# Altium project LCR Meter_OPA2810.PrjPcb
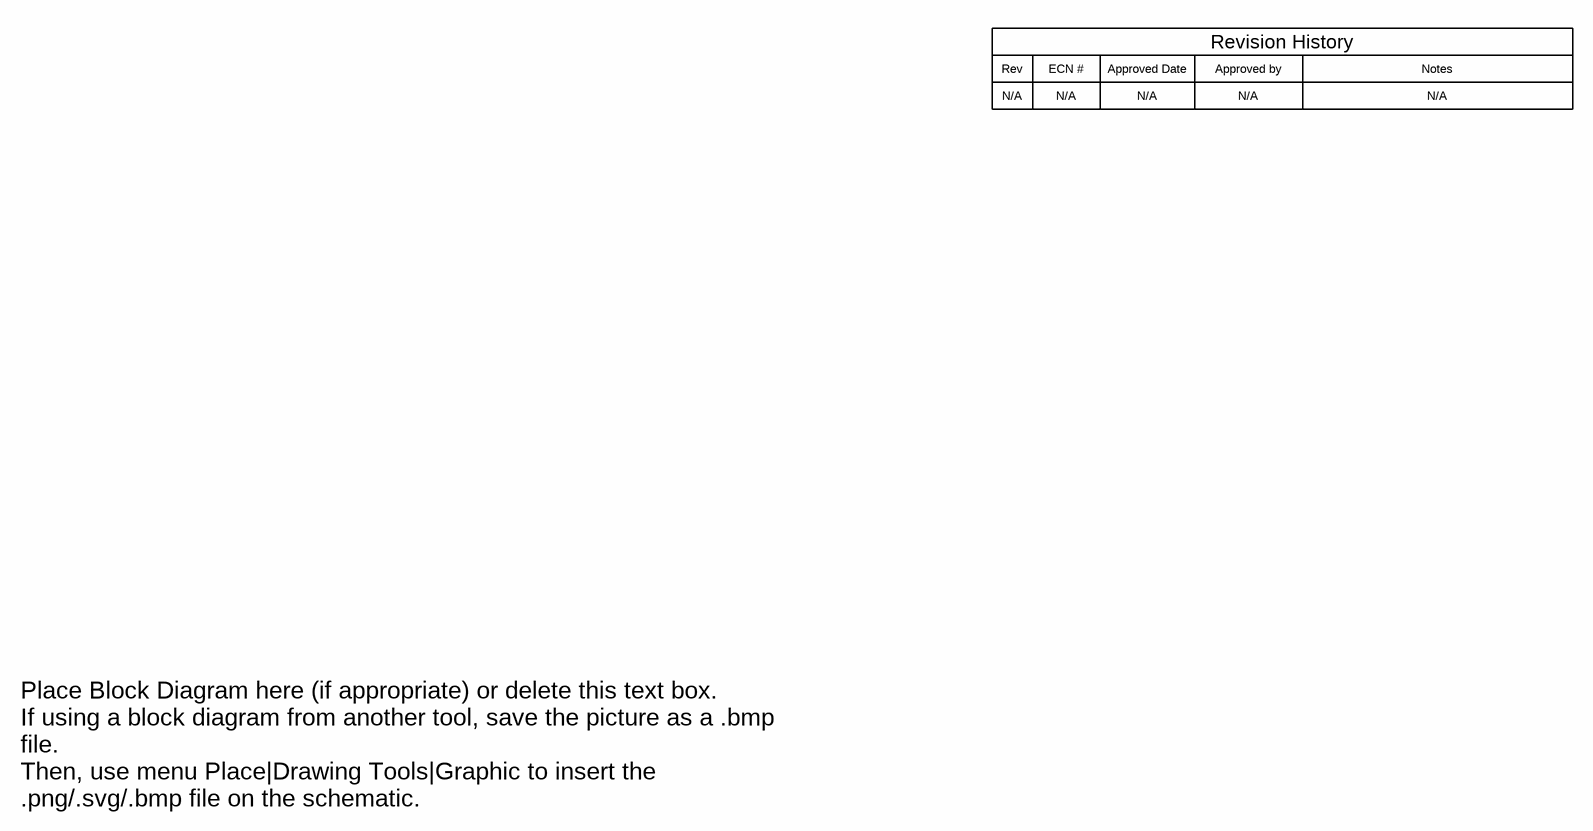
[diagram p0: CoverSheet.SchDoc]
CopyrightYear: 2018; PCB_Layout: Prasanth; PCB_Rev: _A; PRJ_Customer: Public Release; PRJ_Engineer: Adesh; PRJ_Number: LCR Meter_OPA2810; PRJ_Title: LCR Meter_OPA2810; SCH_Rev: _E1; TechSupport: http://www.ti.com/support; TID: N/A
5 sheets, 154 parts. Net scope: global (net labels, ports and power ports of the same name join across sheets).
Board file: LCR Meter_OPA2810_Rev_A.PcbDoc
Sheets:
  CoverSheet.SchDoc
  Power Supply.SchDoc
  BlankSheet.SchDoc
  EVM_Hardware.SchDoc
  VCA.SchDoc

## Sheet CoverSheet.SchDoc
size 431 x 279 mm; Date: Not shown in title block; ApprovedBy: Not shown in title block; CheckedBy: Not shown in title block; Author: Not shown in title block; CompanyName: Not shown in title block; Engineer: Not shown in title block; Organization: Not shown in title block; Address1: Not shown in title block; Address2: Not shown in title block; Address3: Not shown in title block; Address4: Not shown in title block; DocumentNumber: 1; Revision: Use project parameter SCH_Rev; SheetNumber: 1; SheetTotal: 3; PageSetup: Record=PageOptions¦CenterHorizontal=True¦CenterVertical=True¦PrintScale=1.00¦XCorrection=1.00¦YCorrection=1.00¦PrintKind=0¦BorderSize=5000000¦LeftOffset=0¦BottomOffset=0¦Orientation=2¦PaperLength=1000¦PaperWidth=1000¦Scale=100¦PaperSource=15¦PrintQuality=600¦MediaType=1¦DitherType=10¦PaperKind=Letter¦PrintScaleMode=1

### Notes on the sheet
- Rev
- N/A
- ECN #
- Approved Date
- Approved by
- Revision History
- Notes
- Place Block Diagram here (if appropriate) or delete this text box.
  If using a block diagram from another tool, save the picture as a .bmp file.
  Then, use menu Place|Drawing Tools|Graphic to insert the .png/.svg/.bmp file on the schematic.

## Sheet Power Supply.SchDoc
size 431 x 279 mm; Date: Not shown in title block; ApprovedBy: Not shown in title block; CheckedBy: Not shown in title block; Author: Not shown in title block; CompanyName: Not shown in title block; Engineer: Not shown in title block; Organization: Not shown in title block; Address1: Not shown in title block; Address2: Not shown in title block; Address3: Not shown in title block; Address4: Not shown in title block; DocumentNumber: 1; Revision: Use project parameter SCH_Rev; SheetNumber: 2; SheetTotal: 3; PageSetup: Record=PageOptions¦CenterHorizontal=True¦CenterVertical=True¦PrintScale=1.00¦XCorrection=1.00¦YCorrection=1.00¦PrintKind=0¦BorderSize=5000000¦LeftOffset=0¦BottomOffset=0¦Orientation=2¦PaperLength=1000¦PaperWidth=1000¦Scale=100¦PaperSource=15¦PrintQuality=600¦MediaType=1¦DitherType=10¦PaperKind=Letter¦PrintScaleMode=1

## Sheet BlankSheet.SchDoc
size 431 x 279 mm; Date: Not shown in title block; ApprovedBy: Not shown in title block; CheckedBy: Not shown in title block; Author: Not shown in title block; CompanyName: Not shown in title block; Engineer: Not shown in title block; Organization: Not shown in title block; Address1: Not shown in title block; Address2: Not shown in title block; Address3: Not shown in title block; Address4: Not shown in title block; DocumentNumber: 1; Revision: Use project parameter SCH_Rev; SheetNumber: 2; SheetTotal: 3; PageSetup: Record=PageOptions¦CenterHorizontal=True¦CenterVertical=True¦PrintScale=1.00¦XCorrection=1.00¦YCorrection=1.00¦PrintKind=0¦BorderSize=5000000¦LeftOffset=0¦BottomOffset=0¦Orientation=2¦PaperLength=1000¦PaperWidth=1000¦Scale=100¦PaperSource=15¦PrintQuality=600¦MediaType=1¦DitherType=10¦PaperKind=Letter¦PrintScaleMode=1
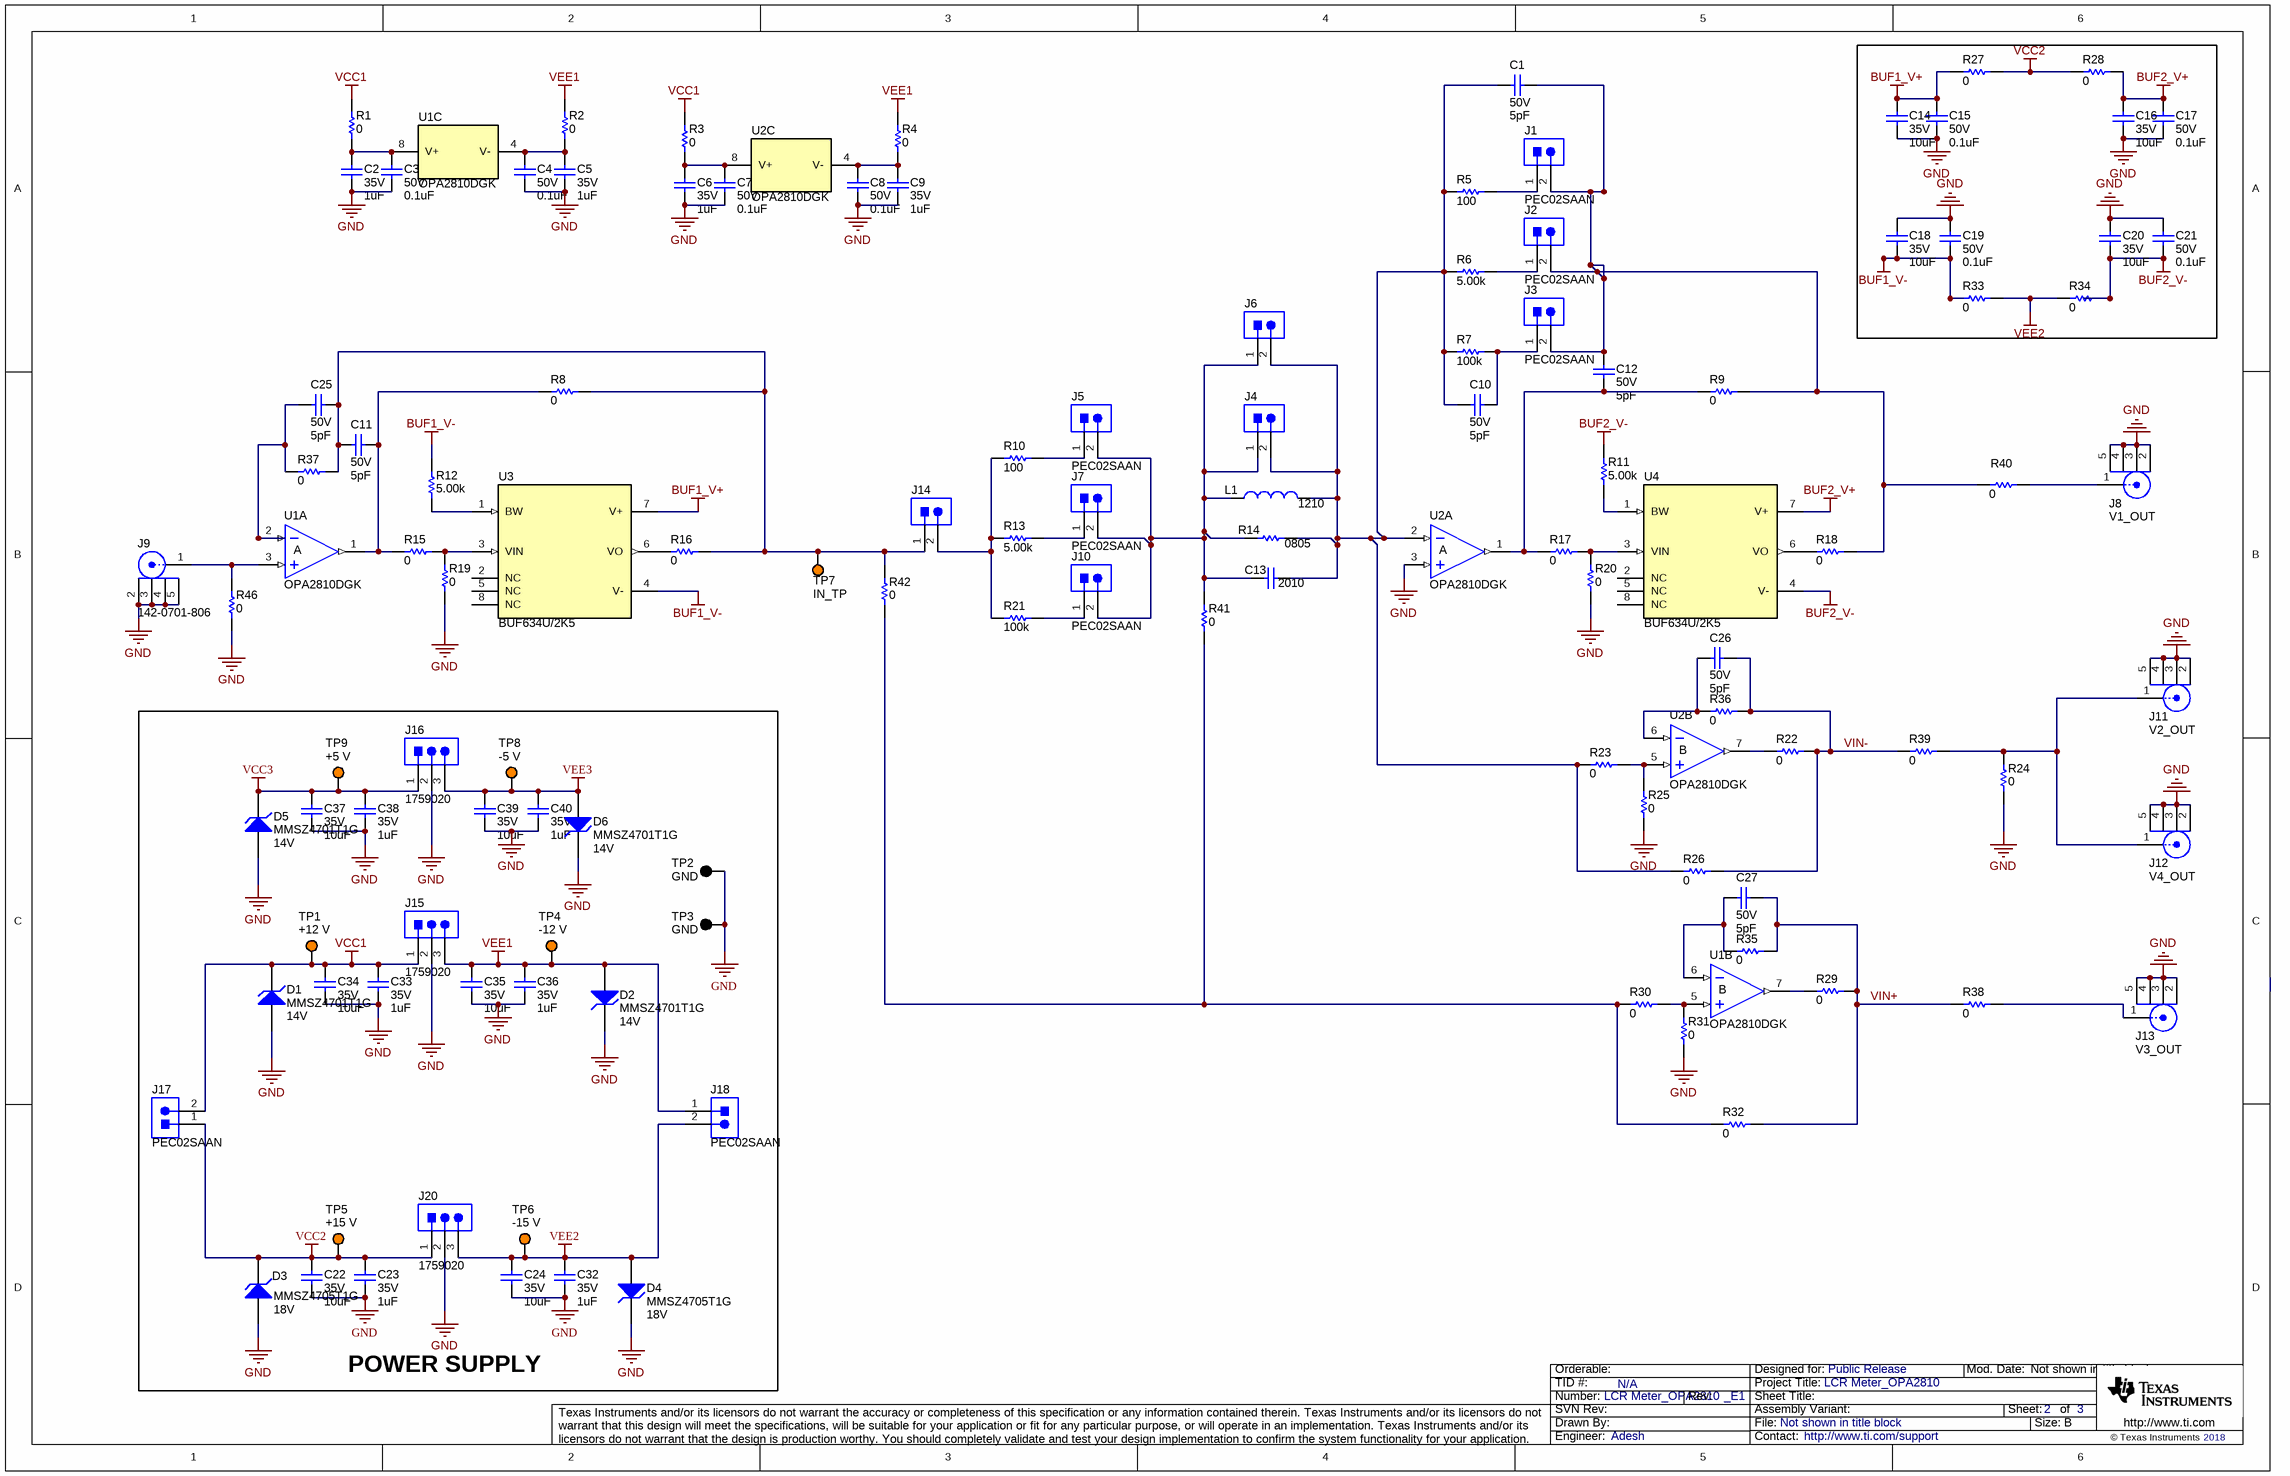
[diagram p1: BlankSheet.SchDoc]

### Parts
C1  VDC_V: 50V  ValueDisplayed: 5pF  [0402]  (hidden comment: GRM1555C1H5R0CA01D)
C2  VDC_V: 35V  ValueDisplayed: 1uF  [0603]  (hidden comment: C1608X7R1V105K080AC)
C3  VDC_V: 50V  ValueDisplayed: 0.1uF  [0603]  (hidden comment: GRM188R71H104KA93D)
C4  VDC_V: 50V  ValueDisplayed: 0.1uF  [0603]  (hidden comment: GRM188R71H104KA93D)
C5  VDC_V: 35V  ValueDisplayed: 1uF  [0603]  (hidden comment: C1608X7R1V105K080AC)
C6  VDC_V: 35V  ValueDisplayed: 1uF  [0603]  (hidden comment: C1608X7R1V105K080AC)
C7  VDC_V: 50V  ValueDisplayed: 0.1uF  [0603]  (hidden comment: GRM188R71H104KA93D)
C8  VDC_V: 50V  ValueDisplayed: 0.1uF  [0603]  (hidden comment: GRM188R71H104KA93D)
C9  VDC_V: 35V  ValueDisplayed: 1uF  [0603]  (hidden comment: C1608X7R1V105K080AC)
C10  VDC_V: 50V  ValueDisplayed: 5pF  [0402]  (hidden comment: GRM1555C1H5R0CA01D)
C11  VDC_V: 50V  ValueDisplayed: 5pF  [0402]  (hidden comment: GRM1555C1H5R0CA01D)
C12  VDC_V: 50V  ValueDisplayed: 5pF  [0402]  (hidden comment: GRM1555C1H5R0CA01D)
C13  Used in BOM report  [2010]  (value not drawn)
C14  VDC_V: 35V  ValueDisplayed: 10uF  [0805_HV]  (hidden comment: GRM21BC8YA106KE11L)
C15  VDC_V: 50V  ValueDisplayed: 0.1uF  [0603]  (hidden comment: GRM188R71H104KA93D)
C16  VDC_V: 35V  ValueDisplayed: 10uF  [0805_HV]  (hidden comment: GRM21BC8YA106KE11L)
C17  VDC_V: 50V  ValueDisplayed: 0.1uF  [0603]  (hidden comment: GRM188R71H104KA93D)
C18  VDC_V: 35V  ValueDisplayed: 10uF  [0805_HV]  (hidden comment: GRM21BC8YA106KE11L)
C19  VDC_V: 50V  ValueDisplayed: 0.1uF  [0603]  (hidden comment: GRM188R71H104KA93D)
C20  VDC_V: 35V  ValueDisplayed: 10uF  [0805_HV]  (hidden comment: GRM21BC8YA106KE11L)
C21  VDC_V: 50V  ValueDisplayed: 0.1uF  [0603]  (hidden comment: GRM188R71H104KA93D)
C22  VDC_V: 35V  ValueDisplayed: 10uF  [0805_HV]  (hidden comment: GRM21BC8YA106KE11L)
C23  VDC_V: 35V  ValueDisplayed: 1uF  [0603]  (hidden comment: C1608X7R1V105K080AC)
C24  VDC_V: 35V  ValueDisplayed: 10uF  [0805_HV]  (hidden comment: GRM21BC8YA106KE11L)
C25  VDC_V: 50V  ValueDisplayed: 5pF  [0402]  (hidden comment: GRM1555C1H5R0CA01D)
C26  VDC_V: 50V  ValueDisplayed: 5pF  [0402]  (hidden comment: GRM1555C1H5R0CA01D)
C27  VDC_V: 50V  ValueDisplayed: 5pF  [0402]  (hidden comment: GRM1555C1H5R0CA01D)
C32  VDC_V: 35V  ValueDisplayed: 1uF  [0603]  (hidden comment: C1608X7R1V105K080AC)
C33  VDC_V: 35V  ValueDisplayed: 1uF  [0603]  (hidden comment: C1608X7R1V105K080AC)
C34  VDC_V: 35V  ValueDisplayed: 10uF  [0805_HV]  (hidden comment: GRM21BC8YA106KE11L)
C35  VDC_V: 35V  ValueDisplayed: 10uF  [0805_HV]  (hidden comment: GRM21BC8YA106KE11L)
C36  VDC_V: 35V  ValueDisplayed: 1uF  [0603]  (hidden comment: C1608X7R1V105K080AC)
C37  VDC_V: 35V  ValueDisplayed: 10uF  [0805_HV]  (hidden comment: GRM21BC8YA106KE11L)
C38  VDC_V: 35V  ValueDisplayed: 1uF  [0603]  (hidden comment: C1608X7R1V105K080AC)
C39  VDC_V: 35V  ValueDisplayed: 10uF  [0805_HV]  (hidden comment: GRM21BC8YA106KE11L)
C40  VDC_V: 35V  ValueDisplayed: 1uF  [0603]  (hidden comment: C1608X7R1V105K080AC)
D1  MMSZ4701T1G  value 14V  [SOD-123]
D2  MMSZ4701T1G  value 14V  [SOD-123]
D3  MMSZ4705T1G  value 18V  [SOD-123]
D4  MMSZ4705T1G  value 18V  [SOD-123]
D5  MMSZ4701T1G  value 14V  [SOD-123]
D6  MMSZ4701T1G  value 14V  [SOD-123]
J1  PEC02SAAN  [CONN_PEC02SAAN]
J2  PEC02SAAN  [CONN_PEC02SAAN]
J3  PEC02SAAN  [CONN_PEC02SAAN]
J4  PEC02SAAN  [CONN_PEC02SAAN]  (value not drawn)
J5  PEC02SAAN  [CONN_PEC02SAAN]
J6  PEC02SAAN  [CONN_PEC02SAAN]  (value not drawn)
J7  PEC02SAAN  [CONN_PEC02SAAN]
J8  V1_OUT  [Johnson_142-0701-80x]
J9  142-0701-806  [Johnson_142-0701-80x]
J10  PEC02SAAN  [CONN_PEC02SAAN]
J11  V2_OUT  [Johnson_142-0701-80x]
J12  V4_OUT  [Johnson_142-0701-80x]
J13  V3_OUT  [Johnson_142-0701-80x]
J14  PEC02SAAN  [CONN_PEC02SAAN]  (value not drawn)
J15  1759020  [Phoenix_1759020]
J16  1759020  [Phoenix_1759020]
J17  PEC02SAAN  [CONN_PEC02SAAN]
J18  PEC02SAAN  [CONN_PEC02SAAN]
J20  1759020  [Phoenix_1759020]
L1  Used in BOM report  [1210]  (value not drawn)
R1  ValueDisplayed: 0  [0603]  (hidden comment: RC0603JR-070RL)
R2  ValueDisplayed: 0  [0603]  (hidden comment: RC0603JR-070RL)
R3  ValueDisplayed: 0  [0603]  (hidden comment: RC0603JR-070RL)
R4  ValueDisplayed: 0  [0603]  (hidden comment: RC0603JR-070RL)
R5  ValueDisplayed: 100  [0402]  (hidden comment: RG1005P-101-B-T5)
R6  ValueDisplayed: 5.00k  [0402]  (hidden comment: PNM0402E5001BST1)
R7  ValueDisplayed: 100k  [0603]  (hidden comment: RG1608P-104-B-T5)
R8  ValueDisplayed: 0  [0603]  (hidden comment: RC0603JR-070RL)
R9  ValueDisplayed: 0  [0603]  (hidden comment: RC0603JR-070RL)
R10  ValueDisplayed: 100  [0402]  (hidden comment: RG1005P-101-B-T5)
R11  ValueDisplayed: 5.00k  [0402]  (hidden comment: PNM0402E5001BST1)
R12  ValueDisplayed: 5.00k  [0402]  (hidden comment: PNM0402E5001BST1)
R13  ValueDisplayed: 5.00k  [0402]  (hidden comment: PNM0402E5001BST1)
R14  Used in BOM report  [0805]  (value not drawn)
R15  ValueDisplayed: 0  [0603]  (hidden comment: RC0603JR-070RL)
R16  ValueDisplayed: 0  [0603]  (hidden comment: RC0603JR-070RL)
R17  ValueDisplayed: 0  [0603]  (hidden comment: RC0603JR-070RL)
R18  ValueDisplayed: 0  [0603]  (hidden comment: RC0603JR-070RL)
R19  ValueDisplayed: 0  [0603]  (hidden comment: RC0603JR-070RL)
R20  ValueDisplayed: 0  [0603]  (hidden comment: RC0603JR-070RL)
R21  ValueDisplayed: 100k  [0603]  (hidden comment: RG1608P-104-B-T5)
R22  ValueDisplayed: 0  [0603]  (hidden comment: RC0603JR-070RL)
R23  ValueDisplayed: 0  [0603]  (hidden comment: RC0603JR-070RL)
R24  ValueDisplayed: 0  [0603]  (hidden comment: RC0603JR-070RL)
R25  ValueDisplayed: 0  [0603]  (hidden comment: RC0603JR-070RL)
R26  ValueDisplayed: 0  [0603]  (hidden comment: RC0603JR-070RL)
R27  ValueDisplayed: 0  [0603]  (hidden comment: RC0603JR-070RL)
R28  ValueDisplayed: 0  [0603]  (hidden comment: RC0603JR-070RL)
R29  ValueDisplayed: 0  [0603]  (hidden comment: RC0603JR-070RL)
R30  ValueDisplayed: 0  [0603]  (hidden comment: RC0603JR-070RL)
R31  ValueDisplayed: 0  [0603]  (hidden comment: RC0603JR-070RL)
R32  ValueDisplayed: 0  [0603]  (hidden comment: RC0603JR-070RL)
R33  ValueDisplayed: 0  [0603]  (hidden comment: RC0603JR-070RL)
R34  ValueDisplayed: 0  [0603]  (hidden comment: RC0603JR-070RL)
R35  ValueDisplayed: 0  [0603]  (hidden comment: RC0603JR-070RL)
R36  ValueDisplayed: 0  [0603]  (hidden comment: RC0603JR-070RL)
R37  ValueDisplayed: 0  [0603]  (hidden comment: RC0603JR-070RL)
R38  ValueDisplayed: 0  [0603]  (hidden comment: RC0603JR-070RL)
R39  ValueDisplayed: 0  [0603]  (hidden comment: RC0603JR-070RL)
R40  ValueDisplayed: 0  [0603]  (hidden comment: RC0603JR-070RL)
R41  ValueDisplayed: 0  [0603]  (hidden comment: RC0603JR-070RL)
R42  ValueDisplayed: 0  [0603]  (hidden comment: RC0603JR-070RL)
R46  ValueDisplayed: 0  [0603]  (hidden comment: RC0603JR-070RL)
TP1  +12 V  [Keystone5013]
TP2  GND  [Keystone5011]
TP3  GND  [Keystone5011]
TP4  -12 V  [Keystone5013]
TP5  +15 V  [Keystone5013]
TP6  -15 V  [Keystone5013]
TP7  IN_TP  [Keystone5013]
TP8  -5 V  [Keystone5013]
TP9  +5 V  [Keystone5013]
U1  OPA2810DGK  [DGK0008A_N]  (parts A,B,C of 3)
U2  OPA2810DGK  [DGK0008A_N]  (parts A,B,C of 3)
U3  BUF634U/2K5  [D0008A_N]
U4  BUF634U/2K5  [D0008A_N]

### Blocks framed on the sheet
POWER SUPPLY: C22-C24 C32-C40 D1-D6 J15-J18 J20 TP1-TP6 TP8 TP9

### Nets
BUF1_V+: C14.1 C15.1 R27.2 U3.7(V+)
BUF1_V-: C18.2 C19.2 R12.2 R33.2 U3.4(V-)
BUF2_V+: C16.1 C17.1 R28.1 U4.7(V+)
BUF2_V-: C20.2 C21.2 R11.2 R34.1 U4.4(V-)
GND: C2.2 C3.2 C4.2 C5.2 C6.2 C7.2 C8.2 C9.2 C14.2 C15.2 C16.2 C17.2 C18.1 C19.1 C20.1 C21.1 C22.2 C23.2 C24.2 C32.1 C33.1 C34.2 C35.2 C36.1 C37.2 C38.1 C39.2 C40.1 D1.2(A) D2.1(K) D3.2(A) D4.1(K) D5.2(A) D6.1(K) J8.2 J8.3 J8.4 J8.5 J9.2 J9.3 J9.4 J9.5 J11.2 J11.3 J11.4 J11.5 J12.2 J12.3 J12.4 J12.5 J13.2 J13.3 J13.4 J13.5 J15.2 J16.2 J20.2 R19.1 R20.1 R24.1 R25.1 R31.1 R46.1 TP2.1 TP3.1 U2.3(IN+)
VCC1: C33.2 C34.1 D1.1(K) J15.1 J17.2 R1.2 R3.2 TP1.1
VCC2: C22.1 C23.1 D3.1(K) J17.1 J20.1 R27.1 R28.2 TP5.1
VCC3: C37.1 C38.2 D5.1(K) J16.1 TP9.1
VEE1: C35.1 C36.2 D2.2(A) J15.3 J18.1 R2.2 R4.2 TP4.1
VEE2: C24.1 C32.2 D4.2(A) J18.2 J20.3 R33.1 R34.2 TP6.1
VEE3: C39.1 C40.2 D6.2(A) J16.3 TP8.1
VIN+: C27.1 R29.2 R32.2 R35.2 R38.1
VIN-: C26.1 R22.2 R26.2 R36.2 R39.1
NetC1_1: C1.1 C12.1 J1.2 J2.2 J3.2 R9.2 R18.2 R40.1
NetC1_2: C1.2 C10.2 C13.1 J4.2 J6.2 L1.2 R5.1 R6.1 R7.1 R14.2 R23.1 R26.1 U2.2(IN-)
NetC2_1: C2.1 C3.1 R1.1 U1.8(V+)
NetC4_1: C4.1 C5.1 R2.1 U1.4(V-)
NetC6_1: C6.1 C7.1 R3.1 U2.8(V+)
NetC8_1: C8.1 C9.1 R4.1 U2.4(V-)
NetC10_1: C10.1 J3.1 R7.2
NetC11_1: C11.1 R8.1 R15.1 U1.1(OUT)
NetC11_2: C11.2 C25.1 J14.1 R8.2 R16.2 R37.2 R42.2 TP7.1
NetC12_2: C12.2 R9.1 R17.1 U2.1(OUT)
NetC13_2: C13.2 J4.1 J5.2 J6.1 J7.2 J10.2 L1.1 R14.1 R41.2
NetC25_2: C25.2 R37.1 U1.2(IN-)
NetC26_2: C26.2 R36.1 U2.6(IN-)
NetC27_2: C27.2 R35.1 U1.6(IN-)
NetJ1_1: J1.1 R5.2
NetJ2_1: J2.1 R6.2
NetJ5_1: J5.1 R10.2
NetJ7_1: J7.1 R13.2
NetJ8_1: J8.1 R40.2
NetJ9_1: J9.1 R46.2 U1.3(IN+)
NetJ10_1: J10.1 R21.2
NetJ11_1: J11.1 J12.1 R24.2 R39.2
NetJ13_1: J13.1 R38.2
NetJ14_2: J14.2 R10.1 R13.1 R21.1
NetR11_1: R11.1 U4.1(BW)
NetR12_1: R12.1 U3.1(BW)
NetR15_2: R15.2 R19.2 U3.3(VIN)
NetR16_1: R16.1 U3.6(VO)
NetR17_2: R17.2 R20.2 U4.3(VIN)
NetR18_1: R18.1 U4.6(VO)
NetR22_1: R22.1 U2.7(OUT)
NetR23_2: R23.2 R25.2 U2.5(IN+)
NetR29_1: R29.1 U1.7(OUT)
NetR30_1: R30.1 R32.1 R41.1 R42.1
NetR30_2: R30.2 R31.2 U1.5(IN+)

Not connected (* = marked no-connect by the designer): U3 2(NC) 5(NC) 8(NC); U4 2(NC) 5(NC) 8(NC)

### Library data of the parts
C1 C10 C12 = CMP-0006480-2: CAP, CERM, 5 pF, 50 V, +/- 5%, C0G/NP0, 0402; Manufacturer: MuRata; TaMin_C: -55°C; Polarized: N; SizeAreaWB_mm2: 3; Value1: Unknown; U/M: EA; Value: 5pF; TaMax_C: 125°C; SizeZ_mm: 0.6; SizeX_mm: 1; SizeY_mm: 0.5; AEC Category: Q200
C2 C5 C6 C9 C23 C32 C33 C36 C38 C40 = CMP-0007052-4: CAP, CERM, 1 uF, 35 V, +/- 10%, X7R, 0603; Manufacturer: TDK; TaMin_C: -55°C; Polarized: N; SizeAreaWB_mm2: 4.68; Value1: Unknown; U/M: EA; Value: 1uF; TaMax_C: 125°C; SizeZ_mm: 1; SizeX_mm: 1.6; SizeY_mm: 0.8; SizeArea_mm2: 1.28; Cap_F: 1µF; AEC Category: Q200
C3 C4 C7 C8 C15 C17 C19 C21 = CMP-0007434-4: CAP, CERM, 0.1 uF, 50 V, +/- 10%, X7R, 0603; Manufacturer: MuRata; TaMin_C: -55°C; Polarized: N; SizeAreaWB_mm2: 4.68; Value1: Unknown; U/M: EA; Value: 0.1uF; TaMax_C: 125°C; SizeZ_mm: 1; SizeX_mm: 1.6; SizeY_mm: 0.8; SizeArea_mm2: 1.28; Cap_F: 100nF; AEC Category: Q200
C11 C25-C27 = CMP-0006480-2: CAP, CERM, 5 pF, 50 V, +/- 5%, C0G/NP0, 0402; Manufacturer: MuRata; TaMin_C: -55°C; Polarized: N; SizeAreaWB_mm2: 3; Value1: Unknown; U/M: EA; Value: 5pF; TaMax_C: 125°C; SizeZ_mm: 0.6; SizeX_mm: 1; SizeY_mm: 0.5; CompType: Capacitor; AEC Category: Q200
C13 = Capacitor: CAP, CERM, xxxF, xxV, [TempCo], xx%, [PackageReference]; Polarized: N; U/M: EA
C14 C16 C18 C20 C22 C24 C34 C35 C37 C39 = CMP-0008273-1: CAP, CERM, 10 uF, 35 V, +/- 10%, X6S, 0805; Manufacturer: MuRata; TaMin_C: -55°C; Polarized: N; SizeAreaWB_mm2: 6.75; Value1: Unknown; U/M: EA; Value: 10uF; TaMax_C: 105°C; SizeZ_mm: 1.45; SizeX_mm: 2; SizeY_mm: 1.25; Cap_Case: 0805; SizeArea_mm2: 2.5; Cap_F: 10µF; AEC Category: Q200
D1 D2 D5 D6 = CMP-0005744-4: Diode, Zener, 14 V, 500 mW, SOD-123; Manufacturer: ON Semiconductor; Power_W: 500mW; SizeX_mm: 3.85; Value1: 0.5W; RJA_CperW: 340; SizeArea_mm2: 6.545; SizeAreaWB_mm2: 13.095; SizeZ_mm: 1.35; AEC Category: Q101; SizeY_mm: 1.7
D3 D4 = CMP-0005747-4: Diode, Zener, 18 V, 500 mW, SOD-123; Manufacturer: ON Semiconductor; SizeAreaWB_mm2: 13.095; SizeArea_mm2: 6.545; SizeX_mm: 3.85; Value1: 0.5W; SizeY_mm: 1.7; Power_W: 500mW; SizeZ_mm: 1.35; RJA_CperW: 340; AEC Category: Q101
J1-J7 J10 J14 J17 J18 = CMP-0002337-1: Header, 100mil, 2x1, Tin, TH; Manufacturer: Sullins Connector Solutions; CNHeader: TRUE; Current_A: 3A; Green_Lifecycle: Not Set; Shrouded: N; Gender: Male; Green_REACh: Incomplete; Voltage_V: 1.8kV; Row_Count: 1; Pitch_mm: 2.54; CT: FALSE; Cert_UL: Y
J8 J11-J13 = CMP-0055821-1: Connector, End launch SMA, 50 ohm, SMT; Manufacturer: Cinch Connectivity; PartNumber: 142-0701-806; CNHeader: FALSE; Green_Lifecycle: Not Set; Green_REACh: Incomplete; CT: TRUE
J9 = CMP-0055821-1: Connector, End launch SMA, 50 ohm, SMT; Manufacturer: Cinch Connectivity; CNHeader: FALSE; Green_Lifecycle: Not Set; Green_REACh: Incomplete; CT: TRUE
J15 J16 J20 = CMP-0055548-1: Header (Shrouded), 5.08mm, 3x1, Tin, R/A, TH; Manufacturer: Phoenix Contact; Cert_VDE: Y; CNHeader: FALSE; Current_A: 12A; Gender: Male; Voltage_V: 320V; Row_Count: 1; Pitch_mm: 5.08
L1 = Inductor: Inductor, [Technology], [Material], xxuH, xxA, x.xx ohm, [MountType]; U/M: EA
R1-R4 R8 R9 R15-R20 R22-R25 R27-R34 R38-R42 R46 = CMP-0025885-5: RES, 0, 5%, 0.1 W, 0603; Manufacturer: Yageo; Power_W: 100mW; TempCo: 200 ppm/C; Value_Code: 0000; Value: 0; EIA_Code: E24; SizeX_mm: 1.6; SizeZ_mm: 1; Value2: 0.1W; SizeArea_mm2: 1.28; AEC Qualified: N; VDC_V: 75V; AEC Category: Q200; SizeY_mm: 0.8; SizeAreaWB_mm2: 4.68
R5 R10 = CMP-0026814-1: RES, 100, 0.1%, 0.063 W, 0402; Manufacturer: Susumu Co Ltd; Power_W: 63mW; TempCo: 25 ppm/C; Value_Code: 100R; U/M: EA; Value: 100; EIA_Code: E192; SizeX_mm: 1; SizeY_mm: 0.5; SizeZ_mm: 0.6; Value2: 0.063W; AEC Category: Q200
R6 R11-R13 = CMP-0026813-1: RES, 5.00 k, 0.1%, 0.05 W, 0402; Manufacturer: Vishay-Dale; Power_W: 50mW; TempCo: 25 ppm/C; Value_Code: 5k00; U/M: EA; Value: 5.00k; Res_ohm: 5k; SizeX_mm: 1; SizeY_mm: 0.5; SizeZ_mm: 0.6; Value2: 0.05W; AEC Qualified: N; VDC_V: 75V; AEC Category: Q200
R7 R21 = CMP-0023405-3: RES, 100 k, 0.1%, 0.1 W, 0603; Manufacturer: Susumu Co Ltd; Power_W: 100mW; TempCo: 25 ppm/C; U/M: EA; Value: 100k; EIA_Code: E192; SizeX_mm: 1.6; SizeY_mm: 0.8; SizeZ_mm: 1; Value2: 0.1W; SizeArea_mm2: 1.28; VDC_V: 75V; AEC Category: Q200
R14 = Resistor: RES, xxx ohm, x%, xW, [PackageReference]; U/M: EA
R26 R35-R37 = CMP-0025885-5: RES, 0, 5%, 0.1 W, 0603; Manufacturer: Yageo; Power_W: 100mW; TempCo: 200 ppm/C; Value_Code: 0000; Value: 0; EIA_Code: E24; SizeX_mm: 1.6; SizeZ_mm: 1; Value2: 0.1W; SizeArea_mm2: 1.28; CompType: Resistor; AEC Qualified: N; VDC_V: 75V; AEC Category: Q200; SizeY_mm: 0.8; SizeAreaWB_mm2: 4.68
TP1 TP4-TP9 = 5013: Test Point, Multipurpose, Orange, TH; Manufacturer: Keystone; CompType: Test Point Loop; ContactFinish: Silver
TP2 TP3 = 5011: Test Point, Multipurpose, Black, TH; Manufacturer: Keystone; CompType: Test Point Loop; ContactFinish: Silver
U1 U2 = CMP-0013308-3: OPA2810DGK, DGK0008A (VSSOP-8); Manufacturer: Texas Instruments; SizeX_mm: 5.05; SizeY_mm: 3.1; CompType: IC; SizeZ_mm: 1.1; SizeArea_mm2: 15.655; SizeAreaWB_mm2: 35.955; U/M: EA
U3 U4 = CMP-0082445-1: 250mA High-Speed Buffer, D0008A (SOIC-8); Alternate Manufacturer: Texas Instruments; SizeAreaWB_mm2: 56.58; Rating: Catalog; SizeZ_mm: 1.75; SizeX_mm: 4.9; SizeY_mm: 6.2; SizeArea_mm2: 30.38; CompType: IC; AEC Qualified: N; AEC Category: Q200

## Sheet EVM_Hardware.SchDoc
size 431 x 279 mm; Date: Not shown in title block; ApprovedBy: Not shown in title block; CheckedBy: Not shown in title block; Author: Not shown in title block; CompanyName: Not shown in title block; Engineer: Not shown in title block; Organization: Not shown in title block; Address1: Not shown in title block; Address2: Not shown in title block; Address3: Not shown in title block; Address4: Not shown in title block; DocumentNumber: 1; Revision: Use project parameter SCH_Rev; SheetNumber: 3; SheetTotal: 3; PageSetup: Record=PageOptions¦CenterHorizontal=True¦CenterVertical=True¦PrintScale=1.00¦XCorrection=1.00¦YCorrection=1.00¦PrintKind=0¦BorderSize=5000000¦LeftOffset=0¦BottomOffset=0¦Orientation=2¦PaperLength=1000¦PaperWidth=1000¦Scale=100¦PaperSource=15¦PrintQuality=600¦MediaType=1¦DitherType=10¦PaperKind=Letter¦PrintScaleMode=1
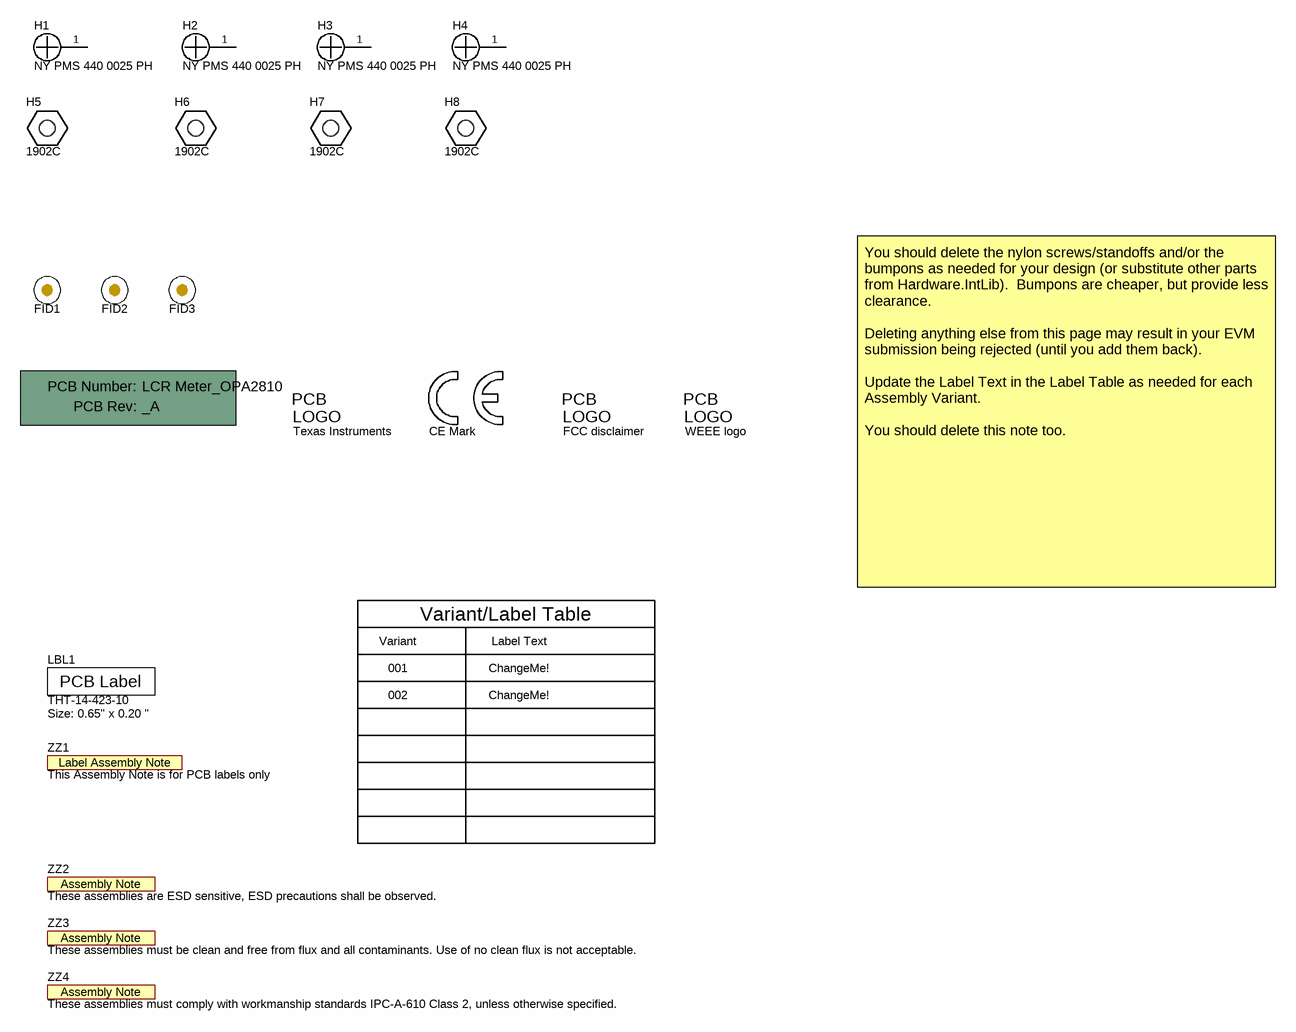
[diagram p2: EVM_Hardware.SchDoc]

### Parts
!PCB1  Printed Circuit Board  (value not drawn)  (mechanical)
FID1  Fiducial  [Fiducial10-20]  (value not drawn)
FID2  Fiducial  [Fiducial10-20]  (value not drawn)
FID3  Fiducial  [Fiducial10-20]  (value not drawn)
H1  NY PMS 440 0025 PH  [NY PMS 440 0025 PH]
H2  NY PMS 440 0025 PH  [NY PMS 440 0025 PH]
H3  NY PMS 440 0025 PH  [NY PMS 440 0025 PH]
H4  NY PMS 440 0025 PH  [NY PMS 440 0025 PH]
H5  1902C  [Keystone_1902C]
H6  1902C  [Keystone_1902C]
H7  1902C  [Keystone_1902C]
H8  1902C  [Keystone_1902C]
LBL1  THT-14-423-10  Note: Size: 0.65" x 0.20 "  [Label_650x200]
Logo1  CE Mark  [CE_Mark_5mm]  (no BOM)
Logo2  Texas Instruments  [TI_Stacked_Overlay_Small]  (no BOM)
Logo3  FCC disclaimer  [FCC_disclaimer]  (no BOM)
Logo4  WEEE logo  [WEEE_Minimum]  (no BOM)
ZZ1  This Assembly Note is for PCB labels only  [AssemblyNoteLabel]  (no BOM)
ZZ2  These assemblies are ESD sensitive, ESD precautions shall be observed.  [AssemblyNote]  (no BOM)
ZZ3  These assemblies must be clean and free from flux and all contaminants. Use of no clean flux is not acceptable.  [AssemblyNote]  (no BOM)
ZZ4  These assemblies must comply with workmanship standards IPC-A-610 Class 2, unless otherwise specified.  [AssemblyNote]  (no BOM)

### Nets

Not connected (* = marked no-connect by the designer): H1 1; H2 1; H3 1; H4 1

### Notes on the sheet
- Variant
- Variant/Label Table
- Label Text
- You should delete the nylon screws/standoffs and/or the bumpons as needed for your design (or substitute other parts from Hardware.IntLib).  Bumpons are cheaper, but provide less clearance.
  Deleting anything else from this page may result in your EVM submission being rejected (until you add them back).
  Update the Label Text in the Label Table as needed for each Assembly Variant.
  You should delete this note too.
- 001
- 002
- ChangeMe!

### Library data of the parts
!PCB1 = CMP-0003618-2: Manufacturer: Any; PartNumber: LCR Meter_OPA2810
FID1-FID3 = CMP-0077181-1: Fiducial mark.  There is nothing to buy or mount.
H1-H4 = CMP-0003617-1: Machine Screw, Round, #4-40 x 1/4, Nylon, Philips panhead; Manufacturer: B&F Fastener Supply; CompType: Hardware
H5-H8 = CMP-0003610-1: Standoff, Hex, 0.5"L #4-40 Nylon; Manufacturer: Keystone; CompType: Hardware
LBL1 = CMP-0003625-1: Thermal Transfer Printable Labels, 0.650" W x 0.200" H - 10,000 per roll; Manufacturer: Brady; CompType: Label
Logo1 = CMP-0074844-1: SymbolCreator: a0412235
Logo2 = CMP-0074838-1: Texas Instrument Corporate Signature; SymbolCreator: a0412235; Lib Reference: TI_Logo; Library Reference: Logo
Logo3 = CMP-0074847-1: FCC_disclaimer; Library Reference: Logo
Logo4 = CMP-0074769-1
ZZ1 = CMP-0003616-3
ZZ2 = CMP-0077236-1
ZZ3 = CMP-0077237-1
ZZ4 = CMP-0077238-1

## Sheet VCA.SchDoc
size 431 x 279 mm; Date: Not shown in title block; ApprovedBy: Not shown in title block; CheckedBy: Not shown in title block; Author: Not shown in title block; CompanyName: Not shown in title block; Engineer: Not shown in title block; Organization: Not shown in title block; Address1: Not shown in title block; Address2: Not shown in title block; Address3: Not shown in title block; Address4: Not shown in title block; DocumentNumber: 1; Revision: Use project parameter SCH_Rev; SheetNumber: 2; SheetTotal: 3; PageSetup: Record=PageOptions¦CenterHorizontal=True¦CenterVertical=True¦PrintScale=1.00¦XCorrection=1.00¦YCorrection=1.00¦PrintKind=0¦BorderSize=5000000¦LeftOffset=0¦BottomOffset=0¦Orientation=2¦PaperLength=1000¦PaperWidth=1000¦Scale=100¦PaperSource=15¦PrintQuality=600¦MediaType=1¦DitherType=10¦PaperKind=Letter¦PrintScaleMode=1
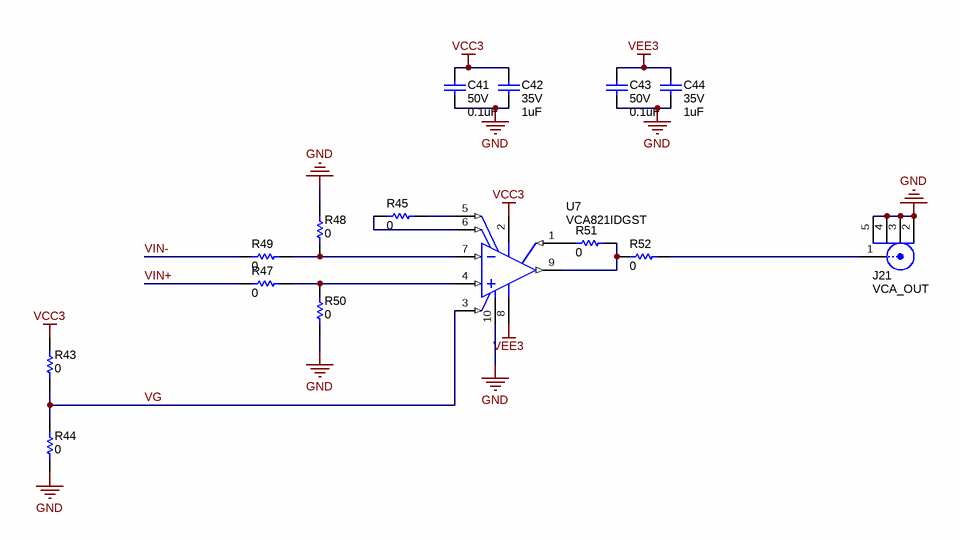
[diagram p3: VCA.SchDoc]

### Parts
C41  VDC_V: 50V  ValueDisplayed: 0.1uF  [0603]  (hidden comment: GRM188R71H104KA93D)
C42  VDC_V: 35V  ValueDisplayed: 1uF  [0603]  (hidden comment: C1608X7R1V105K080AC)
C43  VDC_V: 50V  ValueDisplayed: 0.1uF  [0603]  (hidden comment: GRM188R71H104KA93D)
C44  VDC_V: 35V  ValueDisplayed: 1uF  [0603]  (hidden comment: C1608X7R1V105K080AC)
J21  VCA_OUT  [Johnson_142-0701-80x]
R43  ValueDisplayed: 0  [0603]  (hidden comment: RC0603JR-070RL)
R44  ValueDisplayed: 0  [0603]  (hidden comment: RC0603JR-070RL)
R45  ValueDisplayed: 0  [0603]  (hidden comment: RC0603JR-070RL)
R47  ValueDisplayed: 0  [0603]  (hidden comment: RC0603JR-070RL)
R48  ValueDisplayed: 0  [0603]  (hidden comment: RC0603JR-070RL)
R49  ValueDisplayed: 0  [0603]  (hidden comment: RC0603JR-070RL)
R50  ValueDisplayed: 0  [0603]  (hidden comment: RC0603JR-070RL)
R51  ValueDisplayed: 0  [0603]  (hidden comment: RC0603JR-070RL)
R52  ValueDisplayed: 0  [0603]  (hidden comment: RC0603JR-070RL)
U7  VCA821IDGST  [DGS0010A_L]

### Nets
GND: C41.2 C42.1 C43.2 C44.1 J21.2 J21.3 J21.4 J21.5 R44.2 R48.2 R50.1 U7.10(GND)
VCC3: C41.1 C42.2 R43.1 U7.2(VCC+)
VEE3: C43.1 C44.2 U7.8(VCC-)
VG: R43.2 R44.1 U7.3(VG)
VIN+: R47.1
VIN-: R49.1
NetJ21_1: J21.1 R52.1
NetR45_1: R45.1 U7.6(RG-)
NetR45_2: R45.2 U7.5(RG+)
NetR47_2: R47.2 R50.2 U7.4(VIN+)
NetR48_1: R48.1 R49.2 U7.7(VIN-)
NetR51_1: R51.1 R52.2 U7.9(VOUT)
NetR51_2: R51.2 U7.1(FB)

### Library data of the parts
C41 C43 = CMP-0007434-4: as C3 on sheet BlankSheet
C42 C44 = CMP-0007052-4: as C2 on sheet BlankSheet
J21 = CMP-0055821-1: as J8 on sheet BlankSheet
R43-R45 R47-R52 = CMP-0025885-5: as R1 on sheet BlankSheet
U7 = CMP-0033443-1: Wideband, > 40 dB Adjust Range, Linear in dB Variable Gain Amplifier, -40 to 85 degC, 10-pin SOP (DGS10), Green (RoHS & no Sb/Br); Manufacturer: Texas Instruments; BW @ Acl(MHz): 710; Vs(Min)(V): 7; Vn at Flatband(Typ)(nV/rtHz): 6; Vs(Max)(V): 12; Number of Channels: 1; Vio(Max)(mV): 17; Slew Rate(Typ)(V/us): 2500; Iib(Max)(nA): 25000

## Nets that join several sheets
GND: BlankSheet (66 pins), VCA (12 pins)
VCC3: BlankSheet (5 pins), VCA (C41.1 C42.2 R43.1 U7.2)
VEE3: BlankSheet (5 pins), VCA (C43.1 C44.2 U7.8)
VIN+: BlankSheet (5 pins), VCA (R47.1)
VIN-: BlankSheet (5 pins), VCA (R49.1)

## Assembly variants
001: not fitted C1 C10 C11 C12 C13 C25 C26 C27 FID1 FID2 FID3 L1 R8 R9 R14 R19 R20 R24 R25 R26 R31 R32 R41 R43 R44 R45 R46 R47 R48 R49 R50 R51 R52 U7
